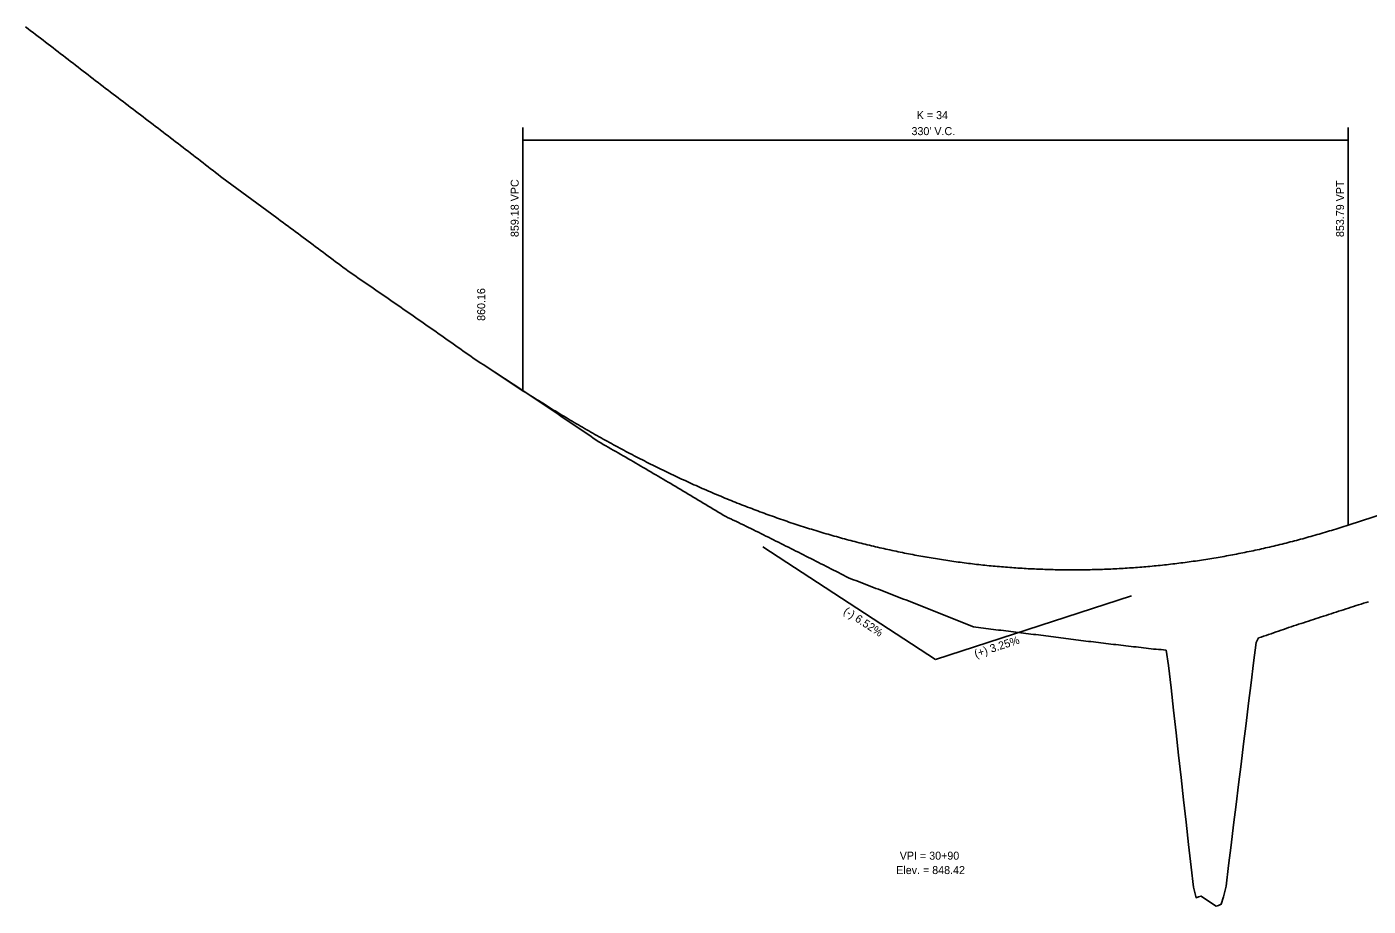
# Model space of a CAD drawing. Extents: x 1738393 to 1742179, y 1214897 to 1219897.
# Drawn here: x 1739606 to 1740142, y 1217782 to 1218134 of the extents above; entities that cross this region are included whole.
import ezdxf

# ---------------------------------------------------------------- set-up
doc = ezdxf.new("R2010")
doc.units = 0
for name, color, linetype in [('RD_DDB_GradeTX', 7, 'Continuous'), ('RD_DDB_Profile_EX', 7, 'Continuous'), ('RD_DDB_Profile_Lbl', 7, 'Continuous'), ('RD_DDB_Profile_PR', 7, 'Continuous'), ('RD_DDB_StripGrade', 7, 'Continuous'), ('RD_DDB_VCLbl', 7, 'Continuous')]:
    doc.layers.add(name, color=color, linetype=linetype)

msp = doc.modelspace()

# ---------------------------------------------------------------- linework, layer by layer
at = {"layer": 'RD_DDB_GradeTX'}
for p in [(1739900.34, 1217926), (1740047.73, 1217906.51)]:
    msp.add_line(p, (1739969.37, 1217881.01), dxfattribs=at)
at = {"layer": 'RD_DDB_Profile_EX'}
for points in [[(1739605.58, 1218133.83), (1739606.58, 1218133.06), (1739607.58, 1218132.29), (1739608.58, 1218131.52), (1739609.58, 1218130.76), (1739610.58, 1218130.01), (1739611.58, 1218129.26), (1739612.58, 1218128.49), (1739613.58, 1218127.72), (1739614.58, 1218126.95), (1739615.58, 1218126.18), (1739616.58, 1218125.41), (1739617.58, 1218124.64), (1739618.58, 1218123.87), (1739619.58, 1218123.1), (1739620.58, 1218122.34), (1739621.58, 1218121.57), (1739622.58, 1218120.8), (1739623.58, 1218120.02), (1739624.58, 1218119.25), (1739625.58, 1218118.48), (1739626.58, 1218117.71), (1739627.58, 1218116.94), (1739628.58, 1218116.17), (1739629.58, 1218115.4), (1739630.58, 1218114.63), (1739631.58, 1218113.86), (1739632.58, 1218113.08), (1739633.58, 1218112.31), (1739634.58, 1218111.54), (1739635.58, 1218110.77), (1739636.58, 1218110.01), (1739637.58, 1218109.25), (1739638.58, 1218108.49), (1739639.58, 1218107.74), (1739640.58, 1218106.98), (1739641.58, 1218106.22), (1739642.58, 1218105.46), (1739643.58, 1218104.7), (1739644.58, 1218103.94), (1739645.58, 1218103.18), (1739646.58, 1218102.41), (1739647.58, 1218101.65), (1739648.58, 1218100.89), (1739649.58, 1218100.13), (1739650.58, 1218099.37), (1739651.58, 1218098.61), (1739652.58, 1218097.85), (1739653.58, 1218097.08), (1739654.58, 1218096.32), (1739655.58, 1218095.56), (1739656.58, 1218094.8), (1739657.58, 1218094.03), (1739658.58, 1218093.27), (1739659.58, 1218092.51), (1739660.58, 1218091.75), (1739661.58, 1218090.99), (1739662.58, 1218090.22), (1739663.58, 1218089.46), (1739664.58, 1218088.69), (1739665.58, 1218087.93), (1739666.58, 1218087.16), (1739667.58, 1218086.4), (1739668.58, 1218085.63), (1739669.58, 1218084.87), (1739670.58, 1218084.1), (1739671.58, 1218083.33), (1739672.58, 1218082.56), (1739673.58, 1218081.79), (1739674.58, 1218081.02), (1739675.58, 1218080.24), (1739676.58, 1218079.47), (1739677.58, 1218078.69), (1739678.58, 1218077.92), (1739679.58, 1218077.14), (1739680.58, 1218076.37), (1739681.58, 1218075.59), (1739682.58, 1218074.81), (1739683.58, 1218074.04), (1739684.58, 1218073.26)], [(1739684.58, 1218073.26), (1739685.58, 1218072.49), (1739686.58, 1218071.77), (1739687.58, 1218071.04), (1739688.58, 1218070.31), (1739689.58, 1218069.58), (1739690.58, 1218068.85), (1739691.58, 1218068.12), (1739692.58, 1218067.39), (1739693.58, 1218066.66), (1739694.58, 1218065.93), (1739695.58, 1218065.2), (1739696.58, 1218064.47), (1739697.58, 1218063.73), (1739698.58, 1218063), (1739699.58, 1218062.27), (1739700.58, 1218061.53), (1739701.58, 1218060.8), (1739702.58, 1218060.06), (1739703.58, 1218059.32), (1739704.58, 1218058.59), (1739705.58, 1218057.85), (1739706.58, 1218057.11), (1739707.58, 1218056.37), (1739708.58, 1218055.63), (1739709.58, 1218054.9), (1739710.58, 1218054.14), (1739711.58, 1218053.4), (1739712.58, 1218052.66), (1739713.58, 1218051.92), (1739714.58, 1218051.18), (1739715.58, 1218050.43), (1739716.58, 1218049.69), (1739717.58, 1218048.95), (1739718.58, 1218048.2), (1739719.58, 1218047.46), (1739720.58, 1218046.71), (1739721.58, 1218045.96), (1739722.58, 1218045.22), (1739723.58, 1218044.47), (1739724.58, 1218043.72), (1739725.58, 1218042.97), (1739726.58, 1218042.22), (1739727.58, 1218041.47), (1739728.58, 1218040.72), (1739729.58, 1218039.97), (1739730.58, 1218039.22), (1739731.58, 1218038.46), (1739732.58, 1218037.71), (1739733.58, 1218036.96), (1739734.58, 1218036.2), (1739735.58, 1218035.49), (1739736.58, 1218034.81), (1739737.58, 1218034.13), (1739738.58, 1218033.45), (1739739.58, 1218032.76), (1739740.58, 1218032.08), (1739741.58, 1218031.4), (1739742.58, 1218030.71), (1739743.58, 1218030.03), (1739744.58, 1218029.34), (1739745.58, 1218028.65), (1739746.58, 1218027.97), (1739747.58, 1218027.28), (1739748.58, 1218026.59), (1739749.58, 1218025.9), (1739750.58, 1218025.21), (1739751.58, 1218024.52), (1739752.58, 1218023.83), (1739753.58, 1218023.14), (1739754.58, 1218022.45), (1739755.58, 1218021.76), (1739756.58, 1218021.07), (1739757.58, 1218020.37), (1739758.58, 1218019.68), (1739759.58, 1218018.99), (1739760.58, 1218018.3), (1739761.58, 1218017.6), (1739762.58, 1218016.91), (1739763.58, 1218016.21), (1739764.58, 1218015.51), (1739765.58, 1218014.81), (1739766.58, 1218014.12), (1739767.58, 1218013.42), (1739768.58, 1218012.72), (1739769.58, 1218012.02), (1739770.58, 1218011.32), (1739771.58, 1218010.62), (1739772.58, 1218009.91), (1739773.58, 1218009.21), (1739774.58, 1218008.51), (1739775.58, 1218007.81), (1739776.58, 1218007.1), (1739777.58, 1218006.4), (1739778.58, 1218005.69), (1739779.58, 1218004.99), (1739780.58, 1218004.28), (1739781.58, 1218003.58), (1739782.58, 1218002.87), (1739783.58, 1218002.16), (1739784.58, 1218001.46)], [(1739784.58, 1218001.46), (1739785.58, 1218000.79), (1739786.58, 1218000.14), (1739787.58, 1217999.49), (1739788.58, 1217998.83), (1739789.58, 1217998.18), (1739790.58, 1217997.52), (1739791.58, 1217996.87), (1739792.58, 1217996.21), (1739793.58, 1217995.56), (1739794.58, 1217994.9), (1739795.58, 1217994.24), (1739796.58, 1217993.58), (1739797.58, 1217992.93), (1739798.58, 1217992.27), (1739799.58, 1217991.61), (1739800.58, 1217990.95), (1739801.58, 1217990.29), (1739802.58, 1217989.63), (1739803.58, 1217988.96), (1739804.58, 1217988.3), (1739805.58, 1217987.64), (1739806.58, 1217986.98), (1739807.58, 1217986.31), (1739808.58, 1217985.65), (1739809.58, 1217984.99), (1739810.58, 1217984.32), (1739811.58, 1217983.65), (1739812.58, 1217982.99), (1739813.58, 1217982.32), (1739814.58, 1217981.65), (1739815.58, 1217980.99), (1739816.58, 1217980.32), (1739817.58, 1217979.65), (1739818.58, 1217978.98), (1739819.58, 1217978.31), (1739820.58, 1217977.64), (1739821.58, 1217976.97), (1739822.58, 1217976.29), (1739823.58, 1217975.62), (1739824.58, 1217974.94), (1739825.58, 1217974.27), (1739826.58, 1217973.59), (1739827.58, 1217972.92), (1739828.58, 1217972.24), (1739829.58, 1217971.56), (1739830.58, 1217970.88), (1739831.58, 1217970.2), (1739832.58, 1217969.52), (1739833.58, 1217968.84), (1739834.58, 1217968.15), (1739835.58, 1217967.53), (1739836.58, 1217966.96), (1739837.58, 1217966.39), (1739838.58, 1217965.82), (1739839.58, 1217965.25), (1739840.58, 1217964.68), (1739841.58, 1217964.11), (1739842.58, 1217963.54), (1739843.58, 1217962.96), (1739844.58, 1217962.39), (1739845.58, 1217961.81), (1739846.58, 1217961.23), (1739847.58, 1217960.65), (1739848.58, 1217960.07), (1739849.58, 1217959.49), (1739850.58, 1217958.9), (1739851.58, 1217958.32), (1739852.58, 1217957.73), (1739853.58, 1217957.15), (1739854.58, 1217956.56), (1739855.58, 1217955.97), (1739856.58, 1217955.38), (1739857.58, 1217954.8), (1739858.58, 1217954.21), (1739859.58, 1217953.62), (1739860.58, 1217953.05), (1739861.58, 1217952.46), (1739862.58, 1217951.87), (1739863.58, 1217951.28), (1739864.58, 1217950.69), (1739865.58, 1217950.09), (1739866.58, 1217949.5), (1739867.58, 1217948.91), (1739868.58, 1217948.31), (1739869.58, 1217947.72), (1739870.58, 1217947.12), (1739871.58, 1217946.53), (1739872.58, 1217945.93), (1739873.58, 1217945.33), (1739874.58, 1217944.74), (1739875.58, 1217944.14), (1739876.58, 1217943.54), (1739877.58, 1217942.94), (1739878.58, 1217942.34), (1739879.58, 1217941.73), (1739880.58, 1217941.13), (1739881.58, 1217940.52), (1739882.58, 1217939.91), (1739883.58, 1217939.3), (1739884.58, 1217938.69)], [(1739884.58, 1217938.69), (1739885.58, 1217938.14), (1739886.58, 1217937.67), (1739887.58, 1217937.19), (1739888.58, 1217936.71), (1739889.58, 1217936.24), (1739890.58, 1217935.75), (1739891.58, 1217935.27), (1739892.58, 1217934.78), (1739893.58, 1217934.29), (1739894.58, 1217933.8), (1739895.58, 1217933.31), (1739896.58, 1217932.81), (1739897.58, 1217932.32), (1739898.58, 1217931.83), (1739899.58, 1217931.34), (1739900.58, 1217930.84), (1739901.58, 1217930.35), (1739902.58, 1217929.85), (1739903.58, 1217929.36), (1739904.58, 1217928.86), (1739905.58, 1217928.36), (1739906.58, 1217927.86), (1739907.58, 1217927.37), (1739908.58, 1217926.87), (1739909.58, 1217926.36), (1739910.58, 1217925.84), (1739911.58, 1217925.34), (1739912.58, 1217924.84), (1739913.58, 1217924.34), (1739914.58, 1217923.84), (1739915.58, 1217923.33), (1739916.58, 1217922.83), (1739917.58, 1217922.33), (1739918.58, 1217921.82), (1739919.58, 1217921.32), (1739920.58, 1217920.81), (1739921.58, 1217920.31), (1739922.58, 1217919.8), (1739923.58, 1217919.3), (1739924.58, 1217918.79), (1739925.58, 1217918.28), (1739926.58, 1217917.77), (1739927.58, 1217917.26), (1739928.58, 1217916.75), (1739929.58, 1217916.25), (1739930.58, 1217915.74), (1739931.58, 1217915.22), (1739932.58, 1217914.71), (1739933.58, 1217914.2), (1739934.58, 1217913.67), (1739935.58, 1217913.26), (1739936.58, 1217912.89), (1739937.58, 1217912.51), (1739938.58, 1217912.13), (1739939.58, 1217911.75), (1739940.58, 1217911.36), (1739941.58, 1217910.98), (1739942.58, 1217910.6), (1739943.58, 1217910.21), (1739944.58, 1217909.83), (1739945.58, 1217909.44), (1739946.58, 1217909.05), (1739947.58, 1217908.67), (1739948.58, 1217908.28), (1739949.58, 1217907.9), (1739950.58, 1217907.51), (1739951.58, 1217907.12), (1739952.58, 1217906.73), (1739953.58, 1217906.34), (1739954.58, 1217905.96), (1739955.58, 1217905.57), (1739956.58, 1217905.18), (1739957.58, 1217904.79), (1739958.58, 1217904.4), (1739959.58, 1217904), (1739960.58, 1217903.59), (1739961.58, 1217903.2), (1739962.58, 1217902.81), (1739963.58, 1217902.42), (1739964.58, 1217902.02), (1739965.58, 1217901.63), (1739966.58, 1217901.24), (1739967.58, 1217900.85), (1739968.58, 1217900.45), (1739969.58, 1217900.06), (1739970.58, 1217899.66), (1739971.58, 1217899.27), (1739972.58, 1217898.88), (1739973.58, 1217898.48), (1739974.58, 1217898.09), (1739975.58, 1217897.69), (1739976.58, 1217897.29), (1739977.58, 1217896.9), (1739978.58, 1217896.5), (1739979.58, 1217896.11), (1739980.58, 1217895.71), (1739981.58, 1217895.31), (1739982.58, 1217894.91), (1739983.58, 1217894.51), (1739984.58, 1217894.09)], [(1740084.58, 1217786.2), (1740085.58, 1217790.49), (1740086.58, 1217798.63), (1740087.58, 1217806.75), (1740088.58, 1217814.88), (1740089.58, 1217823), (1740090.58, 1217831.11), (1740091.58, 1217839.22), (1740092.58, 1217847.33), (1740093.58, 1217855.44), (1740094.58, 1217863.54), (1740095.58, 1217871.63), (1740096.58, 1217879.72), (1740097.58, 1217887.81), (1740098.58, 1217889.6), (1740099.58, 1217889.95), (1740100.58, 1217890.29), (1740101.58, 1217890.64), (1740102.58, 1217890.99), (1740103.58, 1217891.33), (1740104.58, 1217891.68), (1740105.58, 1217892.02), (1740106.58, 1217892.37), (1740107.58, 1217892.72), (1740108.58, 1217893.06), (1740109.58, 1217893.41), (1740110.58, 1217893.74), (1740111.58, 1217894.07), (1740112.58, 1217894.4), (1740113.58, 1217894.73), (1740114.58, 1217895.06), (1740115.58, 1217895.38), (1740116.58, 1217895.71), (1740117.58, 1217896.04), (1740118.58, 1217896.37), (1740119.58, 1217896.7), (1740120.58, 1217897.02), (1740121.58, 1217897.35), (1740122.58, 1217897.68), (1740123.58, 1217898), (1740124.58, 1217898.33), (1740125.58, 1217898.65), (1740126.58, 1217898.98), (1740127.58, 1217899.3), (1740128.58, 1217899.63), (1740129.58, 1217899.95), (1740130.58, 1217900.27), (1740131.58, 1217900.59), (1740132.58, 1217900.91), (1740133.58, 1217901.24), (1740134.58, 1217901.56), (1740135.58, 1217901.88), (1740136.58, 1217902.2), (1740137.58, 1217902.52), (1740138.58, 1217902.84), (1740139.58, 1217903.16), (1740140.58, 1217903.47), (1740141.58, 1217903.79), (1740142.58, 1217904.11)], [(1739984.58, 1217894.09), (1739985.58, 1217893.87), (1739986.58, 1217893.77), (1739987.58, 1217893.65), (1739988.58, 1217893.53), (1739989.58, 1217893.4), (1739990.58, 1217893.28), (1739991.58, 1217893.16), (1739992.58, 1217893.04), (1739993.58, 1217892.92), (1739994.58, 1217892.79), (1739995.58, 1217892.67), (1739996.58, 1217892.55), (1739997.58, 1217892.43), (1739998.58, 1217892.3), (1739999.58, 1217892.18), (1740000.58, 1217892.06), (1740001.58, 1217891.93), (1740002.58, 1217891.81), (1740003.58, 1217891.69), (1740004.58, 1217891.56), (1740005.58, 1217891.44), (1740006.58, 1217891.31), (1740007.58, 1217891.19), (1740008.58, 1217891.06), (1740009.58, 1217890.94), (1740010.58, 1217890.81), (1740011.58, 1217890.67), (1740012.58, 1217890.54), (1740013.58, 1217890.42), (1740014.58, 1217890.29), (1740015.58, 1217890.17), (1740016.58, 1217890.04), (1740017.58, 1217889.91), (1740018.58, 1217889.79), (1740019.58, 1217889.66), (1740020.58, 1217889.54), (1740021.58, 1217889.41), (1740022.58, 1217889.28), (1740023.58, 1217889.16), (1740024.58, 1217889.03), (1740025.58, 1217888.9), (1740026.58, 1217888.77), (1740027.58, 1217888.65), (1740028.58, 1217888.52), (1740029.58, 1217888.39), (1740030.58, 1217888.26), (1740031.58, 1217888.14), (1740032.58, 1217888.01), (1740033.58, 1217887.88), (1740034.58, 1217887.75), (1740035.58, 1217887.63), (1740036.58, 1217887.51), (1740037.58, 1217887.4), (1740038.58, 1217887.28), (1740039.58, 1217887.17), (1740040.58, 1217887.05), (1740041.58, 1217886.94), (1740042.58, 1217886.82), (1740043.58, 1217886.7), (1740044.58, 1217886.59), (1740045.58, 1217886.47), (1740046.58, 1217886.36), (1740047.58, 1217886.24), (1740048.58, 1217886.12), (1740049.58, 1217886.01), (1740050.58, 1217885.89), (1740051.58, 1217885.77), (1740052.58, 1217885.65), (1740053.58, 1217885.54), (1740054.58, 1217885.42), (1740055.58, 1217885.3), (1740056.58, 1217885.18), (1740057.58, 1217885.07), (1740058.58, 1217884.98), (1740059.58, 1217884.94), (1740060.58, 1217884.85), (1740061.58, 1217884.73), (1740062.58, 1217878.65), (1740063.58, 1217869.68), (1740064.58, 1217860.72), (1740065.58, 1217851.76), (1740066.58, 1217842.8), (1740067.58, 1217833.85), (1740068.58, 1217824.9), (1740069.58, 1217815.96), (1740070.58, 1217807.02), (1740071.58, 1217798.08), (1740072.58, 1217790.07), (1740073.58, 1217785.82), (1740074.58, 1217786.17), (1740075.58, 1217786.45), (1740076.58, 1217785.78), (1740077.58, 1217785.12), (1740078.58, 1217784.45), (1740079.58, 1217783.78), (1740080.58, 1217783.11), (1740081.58, 1217782.44), (1740082.58, 1217782.68), (1740083.58, 1217783.23), (1740084.58, 1217786.2)]]:
    msp.add_lwpolyline(points, dxfattribs=at)
at = {"layer": 'RD_DDB_Profile_PR'}
for p, q in [((1739789.37, 1217998.32), (1739804.37, 1217988.55)), ((1740134.37, 1217934.71), (1740269.37, 1217978.64))]:
    msp.add_line(p, q, dxfattribs=at)
msp.add_spline([(1739804.37, 1217988.55), (1739810.97, 1217984.31), (1739817.57, 1217980.2), (1739824.17, 1217976.22), (1739830.77, 1217972.37), (1739837.37, 1217968.65), (1739843.97, 1217965.06), (1739850.57, 1217961.6), (1739857.17, 1217958.26), (1739863.77, 1217955.06), (1739870.37, 1217951.98), (1739876.97, 1217949.03), (1739883.57, 1217946.22), (1739890.17, 1217943.53), (1739896.77, 1217940.97), (1739903.37, 1217938.54), (1739909.97, 1217936.23), (1739916.57, 1217934.06), (1739923.17, 1217932.02), (1739929.77, 1217930.1), (1739936.37, 1217928.32), (1739942.97, 1217926.66), (1739949.57, 1217925.13), (1739956.17, 1217923.73), (1739962.77, 1217922.46), (1739969.37, 1217921.32), (1739975.97, 1217920.31), (1739982.57, 1217919.42), (1739989.17, 1217918.67), (1739995.77, 1217918.04), (1740002.37, 1217917.55), (1740008.97, 1217917.18), (1740015.57, 1217916.94), (1740022.17, 1217916.83), (1740028.77, 1217916.85), (1740035.37, 1217917), (1740041.97, 1217917.28), (1740048.57, 1217917.69), (1740055.17, 1217918.22), (1740061.77, 1217918.89), (1740068.37, 1217919.68), (1740074.97, 1217920.6), (1740081.57, 1217921.65), (1740088.17, 1217922.83), (1740094.77, 1217924.14), (1740101.37, 1217925.58), (1740107.97, 1217927.15), (1740114.57, 1217928.84), (1740121.17, 1217930.67), (1740127.77, 1217932.62), (1740134.37, 1217934.71)], degree=3, dxfattribs=at)
at = {"layer": 'RD_DDB_VCLbl'}
for p, q in [((1739804.37, 1218093.55), (1739804.37, 1217988.55)), ((1740134.37, 1218093.55), (1740134.37, 1217934.71)), ((1739804.37, 1218088.55), (1740134.37, 1218088.55))]:
    msp.add_line(p, q, dxfattribs=at)

# ---------------------------------------------------------------- texts
at = {"layer": 'RD_DDB_GradeTX'}
for s, rotation, p in [('(-) 6.52%', 326.9069, (1739932.33, 1217899.55)), ('(+) 3.25%', 18.0262, (1739985.54, 1217881.67))]:
    msp.add_text(s, height=3.2, rotation=rotation, dxfattribs=at).set_placement(p)
at = {"layer": 'RD_DDB_Profile_Lbl'}
msp.add_text('860.16', height=3.2, rotation=90, dxfattribs=at).set_placement((1739789.37, 1218016.32))
for s, p in [('VPI = 30+90', (1739955.12, 1217801.01)), ('Elev. = 848.42', (1739953.71, 1217795.26))]:
    msp.add_text(s, height=3.2, dxfattribs=at).set_placement(p)
at = {"layer": 'RD_DDB_StripGrade'}
for s, p in [('859.18 VPC', (1739802.76, 1218049.82)), ('853.79 VPT', (1740132.76, 1218049.82))]:
    msp.add_text(s, height=3.2, rotation=90, dxfattribs=at).set_placement(p)
at = {"layer": 'RD_DDB_VCLbl'}
for s, p in [('K = 34', (1739961.91, 1218096.95)), ("330' V.C.", (1739959.81, 1218090.55))]:
    msp.add_text(s, height=3.2, dxfattribs=at).set_placement(p)

doc.saveas('drawing.dxf')
